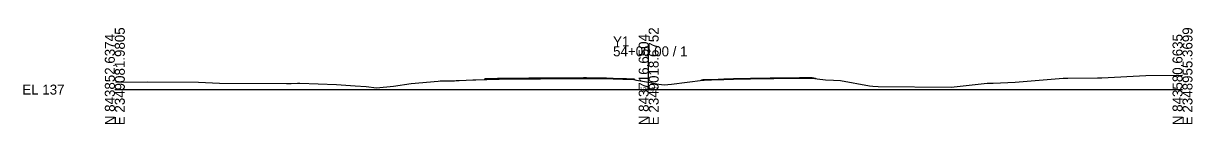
# Model space of a CAD drawing. Extents: x -26 to 2349090, y -10 to 844481.
# Drawn here: x 2274.3 to 2602.8, y 490.3 to 517.3 of the extents above; entities that cross this region are included whole.
import ezdxf

# ---------------------------------------------------------------- set-up
doc = ezdxf.new("R2010")
doc.units = 0
for name, color, linetype in [('Exist Cross Section Cell', 7, 'Continuous'), ('Exist XS Center Line Elevation Label', 7, 'Continuous'), ('Exist XS Ground Line', 7, 'Continuous'), ('Prop CMT Pvmt Surface', 7, 'Continuous'), ('Prop XS Earthwork Shape', 7, 'Continuous')]:
    doc.layers.add(name, color=color, linetype=linetype)

msp = doc.modelspace()

# ---------------------------------------------------------------- linework, layer by layer
at = {"layer": 'Exist Cross Section Cell'}
for p, q in [((2450, 500), (2450, 512.14)), ((2300, 500), (2450, 500)), ((2450, 500), (2600, 500))]:
    msp.add_line(p, q, dxfattribs=at)
at = {"layer": 'Exist XS Ground Line'}
msp.add_lwpolyline([(2300.24, 502.13), (2309.13, 502.22), (2323.47, 502.05), (2329.37, 501.76), (2348.27, 501.71), (2348.89, 501.71), (2349.52, 501.72), (2351.36, 501.77), (2352, 501.81), (2362.32, 501.41), (2367.55, 501.06), (2370.59, 500.83), (2373.5, 500.51), (2378.32, 500.96), (2383.24, 501.67), (2390.85, 502.37), (2391.4, 502.42), (2393.21, 502.43), (2394.65, 502.48), (2395.41, 502.5), (2395.94, 502.52), (2396.77, 502.55), (2398.7, 502.62), (2400.57, 502.71), (2401.47, 502.77), (2403.88, 502.85), (2404.19, 502.86), (2404.54, 502.87), (2406.2, 502.92), (2407.5, 502.94), (2407.99, 502.95), (2409.93, 502.98), (2410.43, 502.99), (2411.84, 503), (2412.49, 503.01), (2413.7, 503.03), (2415.23, 503.04), (2416.37, 503.05), (2417.99, 503.06), (2418.52, 503.06), (2419.62, 503.06), (2420.71, 503.09), (2422.24, 503.1), (2423.46, 503.1), (2424.95, 503.13), (2426.25, 503.12), (2426.87, 503.11), (2428.19, 503.11), (2429, 503.1), (2430.97, 503.12), (2431.41, 503.12), (2431.73, 503.13), (2432.49, 503.13), (2434.09, 503.13), (2434.49, 503.12), (2434.84, 503.12), (2437.22, 503.1), (2438.11, 503.07), (2440.02, 503), (2442.75, 502.94), (2443.77, 502.91), (2445.79, 502.83), (2446.57, 502.69), (2450, 502.07), (2451.81, 501.74), (2452.89, 501.56), (2454.35, 501.31), (2456.44, 501.53), (2465.19, 502.66), (2465.6, 502.68), (2467.62, 502.76), (2469.52, 502.81), (2470.38, 502.83), (2471.16, 502.86), (2473.13, 502.92), (2473.88, 502.94), (2475.91, 502.99), (2477.65, 503.04), (2478.64, 503.05), (2481.44, 503.1), (2483.28, 503.13), (2484.15, 503.14), (2485.18, 503.16), (2487.34, 503.18), (2488.92, 503.19), (2489.63, 503.2), (2491.47, 503.22), (2492.35, 503.23), (2493.38, 503.23), (2494.53, 503.24), (2494.88, 503.24), (2495.92, 503.24), (2497.39, 503.05), (2499.67, 502.75), (2501.94, 502.62), (2503.87, 502.57), (2512.06, 501.1), (2512.97, 500.93), (2514.46, 500.91), (2535.04, 500.68), (2541.75, 501.46), (2545.13, 501.84), (2546.79, 501.83), (2553.01, 502.11), (2566.47, 503.18), (2567.76, 503.21), (2576.07, 503.33), (2577.34, 503.34), (2589.68, 503.98), (2600, 504.05)], dxfattribs=at)
at = {"layer": 'Prop CMT Pvmt Surface'}
for p, q in [((2404, 502.98), (2404.19, 502.99)), ((2404, 502.85), (2404, 502.98)), ((2404.19, 502.99), (2404.54, 503)), ((2404.54, 503), (2406.2, 503.04)), ((2406.2, 503.04), (2407.5, 503.07)), ((2407.5, 503.07), (2407.99, 503.08)), ((2407.99, 503.08), (2409.93, 503.11)), ((2409.93, 503.11), (2410.43, 503.11)), ((2410.43, 503.11), (2411.84, 503.12)), ((2411.84, 503.12), (2412.49, 503.13)), ((2412.49, 503.13), (2413.7, 503.15)), ((2413.7, 503.15), (2415.23, 503.16)), ((2415.23, 503.16), (2416.37, 503.17)), ((2416.37, 503.17), (2417.99, 503.19)), ((2417.99, 503.19), (2418.52, 503.19)), ((2418.52, 503.19), (2419.62, 503.19)), ((2419.62, 503.19), (2420.7, 503.22)), ((2420.7, 503.22), (2422.24, 503.22)), ((2422.24, 503.22), (2423.46, 503.23)), ((2423.46, 503.23), (2424.95, 503.25)), ((2424.95, 503.25), (2426.25, 503.24)), ((2426.25, 503.24), (2426.87, 503.24)), ((2426.87, 503.24), (2428.19, 503.23)), ((2428.19, 503.23), (2429, 503.23)), ((2429, 503.23), (2430.97, 503.24)), ((2430.97, 503.24), (2431.41, 503.25)), ((2431.41, 503.25), (2431.73, 503.26)), ((2431.73, 503.26), (2432.49, 503.26)), ((2432.49, 503.26), (2434.09, 503.25)), ((2434.09, 503.25), (2434.49, 503.25)), ((2434.49, 503.25), (2434.84, 503.24)), ((2434.84, 503.24), (2437.22, 503.23)), ((2437.22, 503.23), (2438.11, 503.2)), ((2438.11, 503.2), (2440.02, 503.13)), ((2440.02, 503.13), (2442.76, 503.06)), ((2442.76, 503.06), (2443.77, 503.03)), ((2443.77, 503.03), (2445.8, 502.95)), ((2445.8, 502.95), (2446, 502.92)), ((2446, 502.92), (2446, 502.79)), ((2464.88, 502.75), (2465.18, 502.79)), ((2464.88, 502.75), (2464.88, 502.62)), ((2465.18, 502.79), (2465.6, 502.8)), ((2465.6, 502.8), (2467.62, 502.88)), ((2467.62, 502.88), (2469.52, 502.93)), ((2469.52, 502.93), (2470.37, 502.96)), ((2470.37, 502.96), (2471.15, 502.98)), ((2471.15, 502.98), (2473.12, 503.05)), ((2473.12, 503.05), (2473.88, 503.07)), ((2473.88, 503.07), (2475.9, 503.12)), ((2475.9, 503.12), (2477.65, 503.16)), ((2477.65, 503.16), (2478.64, 503.18)), ((2478.64, 503.18), (2481.43, 503.23)), ((2481.43, 503.23), (2483.28, 503.25)), ((2483.28, 503.25), (2484.15, 503.27)), ((2484.15, 503.27), (2485.18, 503.28)), ((2485.18, 503.28), (2487.34, 503.31)), ((2487.34, 503.31), (2488.92, 503.31)), ((2488.92, 503.31), (2489.63, 503.32)), ((2489.63, 503.32), (2491.47, 503.34)), ((2491.47, 503.34), (2492.35, 503.36)), ((2492.35, 503.36), (2493.37, 503.36)), ((2493.37, 503.36), (2494.53, 503.36)), ((2494.53, 503.36), (2494.88, 503.36)), ((2494.88, 503.36), (2495.93, 503.36)), ((2495.93, 503.36), (2496.88, 503.24)), ((2496.88, 503.12), (2496.88, 503.24))]:
    msp.add_line(p, q, dxfattribs=at)
at = {"layer": 'Prop XS Earthwork Shape'}
for points in [[(2404.54, 502.87), (2406.2, 502.92), (2407.5, 502.94), (2407.99, 502.95), (2409.93, 502.98), (2410.43, 502.99), (2411.84, 503), (2412.49, 503.01), (2413.7, 503.03), (2415.23, 503.04), (2416.37, 503.05), (2417.99, 503.06), (2418.52, 503.06), (2419.62, 503.06), (2420.71, 503.09), (2422.24, 503.1), (2423.46, 503.1), (2424.95, 503.13), (2426.25, 503.12), (2426.87, 503.11), (2428.19, 503.11), (2429, 503.1), (2430.97, 503.12), (2431.41, 503.12), (2431.73, 503.13), (2432.49, 503.13), (2434.09, 503.13), (2434.49, 503.12), (2434.84, 503.12), (2437.22, 503.1), (2438.11, 503.07), (2440.02, 503), (2442.75, 502.94), (2443.77, 502.91), (2445.79, 502.83), (2446, 502.79), (2446, 502.92), (2445.8, 502.95), (2443.77, 503.03), (2442.76, 503.06), (2440.02, 503.13), (2438.11, 503.2), (2437.22, 503.23), (2434.84, 503.24), (2434.49, 503.25), (2434.09, 503.25), (2432.49, 503.26), (2431.73, 503.26), (2431.41, 503.25), (2430.97, 503.24), (2429, 503.23), (2428.19, 503.23), (2426.87, 503.24), (2426.25, 503.24), (2424.95, 503.25), (2423.46, 503.23), (2422.24, 503.22), (2420.7, 503.22), (2419.62, 503.19), (2418.52, 503.19), (2417.99, 503.19), (2416.37, 503.17), (2415.23, 503.16), (2413.7, 503.15), (2412.49, 503.13), (2411.84, 503.12), (2410.43, 503.11), (2409.93, 503.11), (2407.99, 503.08), (2407.5, 503.07), (2406.2, 503.04), (2404.54, 503), (2404.19, 502.99), (2404, 502.98), (2404, 502.85), (2404.19, 502.86)], [(2473.12, 503.05), (2473.88, 503.07), (2475.9, 503.12), (2477.65, 503.16), (2478.64, 503.18), (2481.43, 503.23), (2483.28, 503.25), (2484.15, 503.27), (2485.18, 503.28), (2487.34, 503.31), (2488.92, 503.31), (2489.63, 503.32), (2491.47, 503.34), (2492.35, 503.36), (2493.37, 503.36), (2494.53, 503.36), (2494.88, 503.36), (2495.93, 503.36), (2496.88, 503.24), (2496.88, 503.12), (2495.92, 503.24), (2494.88, 503.24), (2494.53, 503.24), (2493.38, 503.23), (2492.35, 503.23), (2491.47, 503.22), (2489.63, 503.2), (2488.92, 503.19), (2487.34, 503.18), (2485.18, 503.16), (2484.15, 503.14), (2483.28, 503.13), (2481.44, 503.1), (2478.64, 503.05), (2477.65, 503.04), (2475.91, 502.99), (2473.88, 502.94), (2473.13, 502.92), (2471.16, 502.86), (2470.38, 502.83), (2469.52, 502.81), (2467.62, 502.76), (2465.6, 502.68), (2465.19, 502.66), (2464.88, 502.62), (2464.88, 502.75), (2465.18, 502.79), (2465.6, 502.8), (2467.62, 502.88), (2469.52, 502.93), (2470.37, 502.96), (2471.15, 502.98)]]:
    msp.add_lwpolyline(points, close=True, dxfattribs=at)

# ---------------------------------------------------------------- texts
at = {"layer": 'Exist Cross Section Cell'}
for s, p in [('E 2349081.9805', (2302.8, 490)), ('E 2349018.6752', (2452.8, 490)), ('E 2348955.3699', (2602.8, 490)), ('N 843852.6374', (2300, 490)), ('N 843716.6504', (2450, 490)), ('N 843580.6635', (2600, 490))]:
    msp.add_text(s, height=2.8, rotation=90, dxfattribs=at).set_placement(p)
for s, p in [('Y1', (2440, 512.14)), ('54+00.00 / 1', (2440, 509.34)), ('EL 137', (2274, 498.6))]:
    msp.add_text(s, height=2.8, dxfattribs=at).set_placement(p)
at = {"layer": 'Exist XS Center Line Elevation Label'}
msp.add_text('139.07', height=1.2, dxfattribs=at).set_placement((2447.51, 499.47))

doc.saveas('drawing.dxf')
